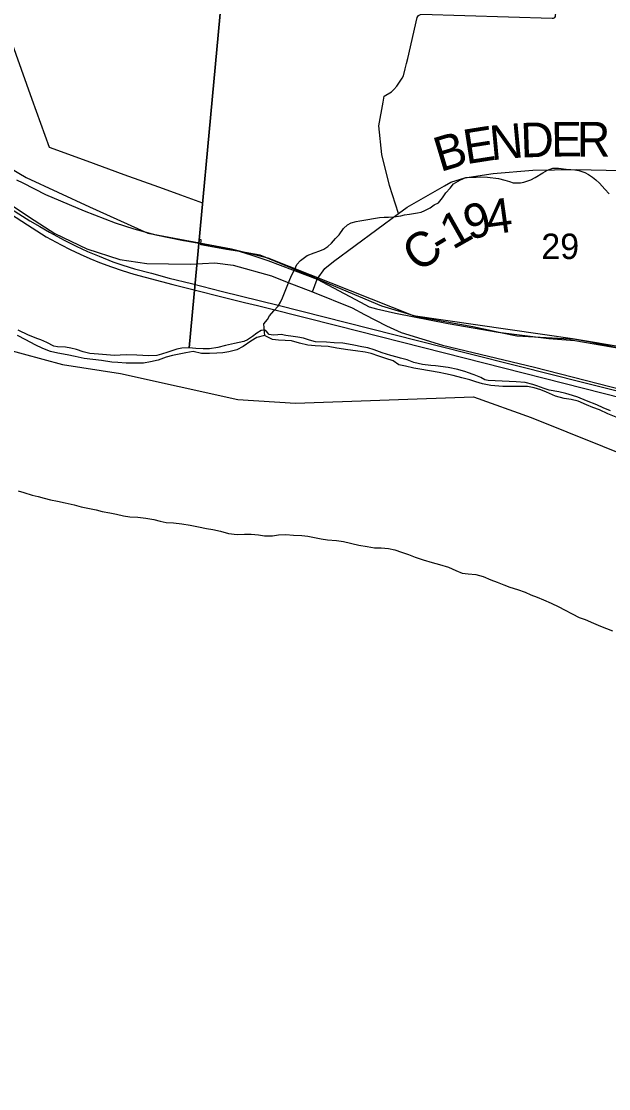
# Model space of a CAD drawing. Extents: x 0 to 43.4, y -8.1 to 22.
# Drawn here: x 4.286 to 5.251, y 14.72 to 16.475 of the extents above; entities that cross this region are included whole.
import ezdxf

# ---------------------------------------------------------------- set-up
doc = ezdxf.new("R2010")
doc.units = 0
for name, color, linetype in [('GM_X_Corporation', 7, 'Continuous'), ('GM_X_County_Road', 7, 'Continuous'), ('GM_X_County_Road_Text', 7, 'Continuous'), ('GM_X_Major_River', 7, 'Continuous'), ('GM_X_Minor_River', 7, 'Continuous'), ('GM_X_Rail_Line', 7, 'Continuous'), ('GM_X_Section_Text', 7, 'Continuous'), ('GM_X_US_Route', 7, 'Continuous')]:
    doc.layers.add(name, color=color, linetype=linetype)

msp = doc.modelspace()

# ---------------------------------------------------------------- linework, layer by layer
at = {"layer": 'GM_X_Corporation'}
for points in [[(4.6148, 16.5127), (4.5615, 15.9381), (4.5497, 15.938), (4.541, 15.9364), (4.5265, 15.9314), (4.5158, 15.9279), (4.5081, 15.9258), (4.4953, 15.9253), (4.4756, 15.9262), (4.4582, 15.927), (4.4384, 15.926), (4.432, 15.9265), (4.4127, 15.9277), (4.398, 15.9292), (4.3871, 15.9318), (4.3765, 15.9358), (4.3671, 15.9379), (4.3581, 15.9393), (4.3452, 15.94), (4.3388, 15.9413), (4.3272, 15.9469), (4.3174, 15.9513), (4.3129, 15.9533), (4.2972, 15.9593), (4.2803, 15.9673)], [(5.2545, 15.8346), (5.2421, 15.8394), (5.2317, 15.8446), (5.2151, 15.8514), (5.2005, 15.8571), (5.1919, 15.8599), (5.181, 15.8632), (5.1693, 15.8662), (5.1538, 15.8688), (5.1452, 15.8717), (5.1332, 15.8761), (5.1268, 15.8782), (5.1143, 15.8811), (5.0992, 15.8827), (5.0534, 15.8845), (5.0478, 15.8858), (5.0411, 15.8897), (5.0302, 15.8938), (5.0193, 15.8978), (5.0163, 15.8987), (5.0035, 15.9028), (4.9873, 15.9058), (4.9665, 15.909), (4.9589, 15.9095), (4.945, 15.911), (4.931, 15.9144), (4.9201, 15.9184), (4.9089, 15.9214), (4.9036, 15.923), (4.8934, 15.9255), (4.8788, 15.9301), (4.866, 15.9353), (4.8551, 15.9386), (4.8457, 15.9399), (4.8321, 15.9429), (4.8238, 15.9446), (4.8144, 15.946), (4.8, 15.9467), (4.7875, 15.9478), (4.7693, 15.9482), (4.7592, 15.9511), (4.7498, 15.954), (4.7404, 15.9561), (4.7328, 15.9571), (4.7207, 15.9589), (4.7128, 15.9602), (4.7075, 15.96), (4.6995, 15.959), (4.6931, 15.9603), (4.689, 15.9646), (4.6861, 15.9677), (4.68, 15.9671), (4.6727, 15.9627), (4.6657, 15.9572), (4.6573, 15.9513), (4.6515, 15.9488), (4.6363, 15.9454), (4.6211, 15.9424), (4.6089, 15.9389), (4.5952, 15.9369), (4.5846, 15.9368), (4.5725, 15.9375), (4.5615, 15.9381), (4.6148, 16.5127)], [(5.2633, 15.9391), (5.2183, 15.9482), (5.1971, 15.9521), (5.1003, 15.9575), (5.0736, 15.9632), (5.0616, 15.9657), (5.028, 15.9729), (4.9363, 15.9895), (4.9313, 15.991), (4.8785, 16.0067), (4.8026, 16.0386), (4.7287, 16.07), (4.7037, 16.0805), (4.6781, 16.0907), (4.6442, 16.0966), (4.641, 16.0972), (4.6227, 16.1004), (4.5807, 16.1077), (4.5815, 16.1162), (4.5787, 16.1167), (4.5791, 16.1217), (4.584, 16.1761), (4.5477, 16.1895), (4.5196, 16.1999), (4.5115, 16.2029), (4.4547, 16.2229), (4.3938, 16.2454), (4.3319, 16.2682), (4.3035, 16.3468), (4.2595, 16.4704)], [(4.2564, 15.9373), (4.3533, 15.9108), (4.4487, 15.8964), (4.6416, 15.8531), (4.7366, 15.8474), (5.0291, 15.858), (5.1241, 15.8235), (5.4143, 15.7071), (5.7095, 15.5281), (5.8045, 15.4515), (6.1414, 15.0677), (6.2843, 14.8736), (6.3804, 14.7818), (6.459, 14.6859)], [(4.2564, 15.9373), (4.3533, 15.9108), (4.4487, 15.8964), (4.6416, 15.8531), (4.7366, 15.8474), (5.0291, 15.858), (5.1241, 15.8235), (5.4143, 15.7071), (5.7095, 15.5281), (5.8045, 15.4515), (6.1354, 15.0635), (6.1959, 14.9813), (6.2842, 14.8736), (6.3804, 14.7818), (6.459, 14.6859)], [(4.2564, 15.9373), (4.3533, 15.9108), (4.4487, 15.8964), (4.6416, 15.8531), (4.7366, 15.8474), (5.0291, 15.858), (5.1241, 15.8235), (5.4143, 15.7071), (5.7095, 15.5281), (5.8045, 15.4515), (6.1414, 15.0677), (6.2843, 14.8736), (6.3804, 14.7818), (6.459, 14.6859)]]:
    msp.add_lwpolyline(points, dxfattribs=at)
at = {"layer": 'GM_X_County_Road'}
msp.add_line((4.7643, 16.0304), (4.7718, 16.0513), dxfattribs=at)
for points in [[(4.9168, 16.3974), (4.919, 16.4059), (4.9213, 16.4144), (4.9364, 16.4819), (4.9388, 16.4849), (4.943, 16.4871), (5.1586, 16.4805), (5.1604, 16.4807), (5.1619, 16.4812), (5.1628, 16.4819), (5.1637, 16.4832), (5.164, 16.4846), (5.2036, 16.8564)], [(4.8803, 16.3426), (4.882, 16.3523), (4.894, 16.3595), (4.8979, 16.3632), (4.9032, 16.3689), (4.912, 16.382), (4.9138, 16.3861), (4.9168, 16.3974)], [(4.9057, 16.1592), (4.8909, 16.2053), (4.8786, 16.2563), (4.8733, 16.3037), (4.8803, 16.3426)], [(4.9057, 16.1592), (4.9201, 16.1698), (4.9815, 16.2049), (4.9919, 16.2111), (5.0148, 16.2178), (5.0612, 16.2251), (5.1266, 16.2309), (5.1979, 16.2316), (5.3458, 16.2284)], [(4.2778, 16.2148), (4.288, 16.2097), (4.3251, 16.1907), (4.3886, 16.1635), (4.4397, 16.1442), (4.4706, 16.1344), (4.5068, 16.1245), (4.5493, 16.1157), (4.5521, 16.1151)], [(4.7718, 16.0513), (4.7847, 16.0688), (4.799, 16.0806), (4.9057, 16.1592)], [(4.5521, 16.1151), (4.5559, 16.1144), (4.6024, 16.1062), (4.6382, 16.0993), (4.6632, 16.0913), (4.691, 16.0822), (4.7718, 16.0513)], [(4.7718, 16.0513), (4.8431, 16.0133), (4.8577, 16.0058), (4.8694, 16.0025), (4.9011, 15.9954), (4.9875, 15.9783), (5.0695, 15.964), (5.1531, 15.9535), (5.1955, 15.9503), (5.3289, 15.9273)]]:
    msp.add_lwpolyline(points, dxfattribs=at)
at = {"layer": 'GM_X_Major_River'}
for points in [[(4.7686, 15.9415), (4.7568, 15.9428), (4.7432, 15.9461), (4.7296, 15.9497), (4.7194, 15.9503), (4.7084, 15.9508), (4.6986, 15.9521), (4.6854, 15.9584), (4.6728, 15.9556), (4.6632, 15.9493), (4.6502, 15.9404), (4.6399, 15.9352), (4.6269, 15.9316), (4.617, 15.9303), (4.6072, 15.9297), (4.595, 15.9291), (4.5818, 15.9293), (4.5681, 15.9322), (4.556, 15.9301), (4.5453, 15.928), (4.5343, 15.9259), (4.5236, 15.923), (4.5103, 15.9179), (4.4981, 15.9151), (4.4867, 15.9133), (4.4772, 15.9131), (4.4582, 15.9134), (4.4442, 15.914), (4.4344, 15.9149), (4.4173, 15.9175), (4.4033, 15.9192), (4.3889, 15.921), (4.3742, 15.9239), (4.3609, 15.9267), (4.3458, 15.9296), (4.3333, 15.9325), (4.3209, 15.9372), (4.3081, 15.9435), (4.2931, 15.9513), (4.2791, 15.9588)], [(5.2637, 15.8243), (5.2501, 15.8298), (5.2362, 15.8361), (5.2252, 15.8401), (5.2147, 15.8448), (5.2011, 15.8504), (5.1898, 15.8532), (5.178, 15.8549), (5.1641, 15.8589), (5.1494, 15.8656), (5.1396, 15.8692), (5.129, 15.8728), (5.118, 15.8745), (5.1082, 15.875), (5.0975, 15.8748), (5.0877, 15.8749), (5.0771, 15.8747), (5.0574, 15.8762), (5.0438, 15.8791), (5.0328, 15.8823), (5.023, 15.8855), (5.0101, 15.8891), (4.9958, 15.8927), (4.9833, 15.8956), (4.9724, 15.898), (4.9568, 15.9006), (4.941, 15.9035), (4.9311, 15.9051), (4.9171, 15.908), (4.9065, 15.9105), (4.8968, 15.9171), (4.8847, 15.9207), (4.8734, 15.9247), (4.8606, 15.929), (4.8507, 15.9315), (4.8352, 15.9336), (4.8223, 15.935), (4.8046, 15.9379), (4.7902, 15.9404), (4.7784, 15.941), (4.7686, 15.9415)], [(4.2801, 15.7033), (4.2899, 15.7001)], [(4.2899, 15.7001), (4.3035, 15.6961), (4.3133, 15.694), (4.3231, 15.6908), (4.3333, 15.6884), (4.345, 15.6859), (4.3575, 15.6835), (4.3722, 15.6802), (4.384, 15.677), (4.4085, 15.6716), (4.4184, 15.6692), (4.4312, 15.6667), (4.4418, 15.6647), (4.4535, 15.6618), (4.4637, 15.6605), (4.477, 15.6599), (4.4903, 15.6582), (4.5035, 15.6557), (4.5137, 15.6533), (4.5235, 15.6512), (4.5356, 15.6503), (4.5497, 15.6489), (4.5633, 15.6468), (4.5769, 15.6439), (4.5898, 15.6414), (4.6007, 15.6394), (4.6128, 15.6365), (4.626, 15.6329), (4.6404, 15.6311), (4.6526, 15.6317), (4.6636, 15.6319), (4.6753, 15.6306), (4.6852, 15.6293), (4.6984, 15.6291), (4.7083, 15.6308), (4.7205, 15.631), (4.733, 15.6301), (4.7466, 15.6295), (4.7565, 15.6285), (4.7678, 15.6261), (4.7788, 15.624), (4.789, 15.6227), (4.8038, 15.6213), (4.8151, 15.6196), (4.8408, 15.6139), (4.8541, 15.6114), (4.8665, 15.6093), (4.8775, 15.6092), (4.8893, 15.6082), (4.8995, 15.6058), (4.9108, 15.6022), (4.9221, 15.5986), (4.9334, 15.5942), (4.9463, 15.5898), (4.9614, 15.585), (4.9731, 15.5818), (4.9878, 15.5778), (5.0002, 15.5723), (5.0104, 15.5676), (5.0206, 15.5666), (5.0328, 15.5653), (5.0448, 15.5621), (5.0577, 15.5569), (5.0678, 15.553), (5.0788, 15.5483), (5.0886, 15.5447), (5.1014, 15.5407), (5.1139, 15.5363), (5.1236, 15.532), (5.1338, 15.528), (5.144, 15.5237), (5.1568, 15.5182), (5.1692, 15.5123), (5.179, 15.5076), (5.1911, 15.5005), (5.2027, 15.495), (5.2125, 15.4915), (5.2265, 15.4852), (5.2382, 15.4804), (5.248, 15.4769), (5.2578, 15.4729)]]:
    msp.add_lwpolyline(points, dxfattribs=at)
at = {"layer": 'GM_X_Minor_River'}
msp.add_lwpolyline([(4.6862, 15.958), (4.6843, 15.9777), (4.6901, 15.9848), (4.6937, 15.9908), (4.7007, 15.999), (4.7077, 16.0069), (4.7117, 16.0137), (4.7149, 16.0205), (4.7172, 16.0261), (4.7237, 16.0427), (4.7272, 16.051), (4.7304, 16.0586), (4.7352, 16.0676), (4.7384, 16.0752), (4.7446, 16.0823), (4.7558, 16.0904), (4.767, 16.0944), (4.7766, 16.0977), (4.7831, 16.1006), (4.7897, 16.105), (4.7955, 16.1106), (4.8022, 16.1181), (4.808, 16.1245), (4.8151, 16.1346), (4.8221, 16.1409), (4.8282, 16.1439), (4.8363, 16.146), (4.8424, 16.1474), (4.8554, 16.1495), (4.8646, 16.1512), (4.8746, 16.1529), (4.8822, 16.1532), (4.8891, 16.1531), (4.8983, 16.154), (4.9098, 16.1553), (4.9155, 16.1571), (4.9236, 16.1581), (4.9305, 16.1592), (4.937, 16.1606), (4.9431, 16.1616), (4.9489, 16.1641), (4.9581, 16.1685), (4.9647, 16.1734), (4.9713, 16.1771), (4.9779, 16.1853), (4.9838, 16.1932), (4.9908, 16.201), (4.9963, 16.2082), (5.0079, 16.2148), (5.0167, 16.2184), (5.027, 16.2194), (5.0335, 16.2193), (5.0412, 16.2195), (5.0519, 16.2193), (5.0705, 16.2167), (5.0804, 16.2143), (5.0884, 16.2118), (5.0941, 16.2098), (5.0998, 16.2097), (5.1063, 16.21), (5.112, 16.211), (5.1232, 16.215), (5.1305, 16.2187), (5.1432, 16.2261), (5.151, 16.2309), (5.1598, 16.2341), (5.169, 16.234), (5.1815, 16.2322), (5.1892, 16.2317), (5.1957, 16.2312), (5.2025, 16.2299), (5.2124, 16.2267), (5.218, 16.2236), (5.2248, 16.2189), (5.2305, 16.215), (5.2361, 16.2092), (5.2451, 16.1995), (5.2522, 16.1918)], dxfattribs=at)
at = {"layer": 'GM_X_Rail_Line'}
for points in [[(4.1978, 16.2749), (4.2934, 16.2188), (4.3976, 16.1704), (4.4935, 16.127), (4.6314, 16.1011), (4.6907, 16.0865), (4.93, 15.9917), (5.1919, 15.9535), (5.3649, 15.9245), (5.4749, 15.8856), (5.5993, 15.8084), (5.7206, 15.6918), (5.9364, 15.5089), (6.0231, 15.4314), (6.3347, 15.0503), (6.5747, 14.7641), (6.7584, 14.6191)], [(4.2558, 16.1752), (4.2993, 16.1475), (4.3158, 16.1379), (4.3316, 16.1288), (4.3441, 16.1218), (4.3573, 16.1148), (4.3758, 16.1057), (4.3941, 16.0971), (4.4137, 16.0889), (4.4362, 16.08), (4.4527, 16.0743), (4.4714, 16.0685), (4.4995, 16.061), (4.5285, 16.0531), (4.5653, 16.0442), (4.6165, 16.0309), (4.7079, 16.0085), (4.8592, 15.9702), (5.0192, 15.9297), (5.1021, 15.9085), (5.2084, 15.8821), (5.2961, 15.8602)], [(4.2678, 16.1589), (4.2957, 16.1405), (4.3266, 16.1211), (4.351, 16.1077), (4.3661, 16.1001), (4.3822, 16.0924), (4.3982, 16.0853), (4.4143, 16.0788), (4.4336, 16.0715), (4.4515, 16.0654), (4.4703, 16.0596), (4.5345, 16.0428), (4.6523, 16.013), (4.674, 16.0078), (4.6937, 16.0028), (4.8042, 15.975), (4.9813, 15.9301), (5.2745, 15.8558)]]:
    msp.add_lwpolyline(points, dxfattribs=at)
at = {"layer": 'GM_X_US_Route'}
msp.add_lwpolyline([(4.2415, 16.1915), (4.2989, 16.1532), (4.3405, 16.1267), (4.3935, 16.1011), (4.4477, 16.0835), (4.4921, 16.0769), (4.5633, 16.076), (4.6039, 16.0783), (4.6341, 16.0743), (4.6969, 16.0566), (4.7228, 16.0466), (4.7643, 16.0304), (4.8298, 16.0039), (4.85, 15.9934), (4.8861, 15.9748), (4.9102, 15.9634), (4.9782, 15.9425), (5.1293, 15.9068), (5.3177, 15.8581)], dxfattribs=at)

# ---------------------------------------------------------------- texts
at = {"layer": 'GM_X_County_Road_Text'}
for s, rotation, p in [('E', 8.9244, (5.0172, 16.2403)), ('N', 5.3773, (5.0583, 16.2468)), ('D', 1.86, (5.1072, 16.2514)), ('E', 0.105, (5.1567, 16.2531)), ('R', 0.0078, (5.1992, 16.2531)), ('B', 16.7306, (4.9745, 16.2274)), ('9', 15.5065, (5.0221, 16.115)), ('4', 7.8907, (5.0539, 16.124)), ('1', 29.4812, (4.995, 16.0992)), ('C', 35.0785, (4.9381, 16.0611)), ('-', 31.1779, (4.9755, 16.0873))]:
    msp.add_text(s, height=0.0568, rotation=rotation, dxfattribs=at).set_placement(p)
at = {"layer": 'GM_X_Section_Text'}
msp.add_text('29', height=0.04186, rotation=0, dxfattribs=at).set_placement((5.1406, 16.0844))

doc.saveas('drawing.dxf')
